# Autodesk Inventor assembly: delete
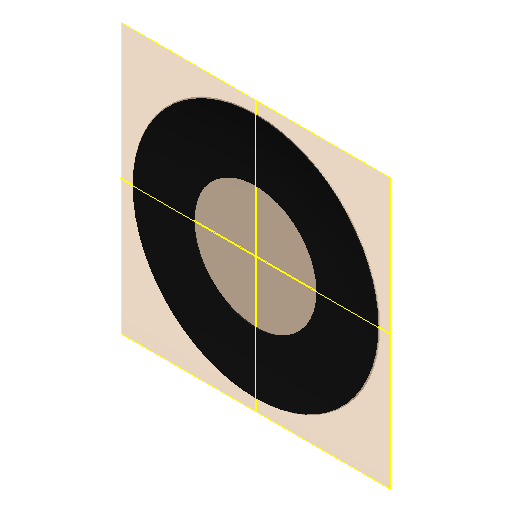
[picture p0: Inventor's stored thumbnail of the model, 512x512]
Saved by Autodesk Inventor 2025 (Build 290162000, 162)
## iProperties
Created: 2025-03
Part Number: delete
Document SubType Name: Assembly
Designer: dansp
Author: dansp
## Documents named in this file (3)
- C:\Users\dansp\Desktop\Model\Model\delete.iam
- C:\Users\dansp\Desktop\Model\Model\bily_delete.ipt
- C:\Users\dansp\Desktop\Model\Model\cerny_delete.ipt
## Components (2 placed, 2 different names)
1. bily_delete:1 — Flush:1, Flush:2, Flush:3, Mate:1, Mate:2
2. cerny_delete:1 — Mate:1, Mate:2
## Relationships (5: Flush 3, Mate 2)
- Flush:1: bily_delete:1
- Flush:2: bily_delete:1
- Flush:3: bily_delete:1
- Mate:1: bily_delete:1 ↔ cerny_delete:1
- Mate:2: bily_delete:1 ↔ cerny_delete:1
